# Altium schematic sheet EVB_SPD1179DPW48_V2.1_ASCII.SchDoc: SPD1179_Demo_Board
size A2; Date: 2024/07/12; Revision: V2.1; SheetNumber: 1; SheetTotal: 1
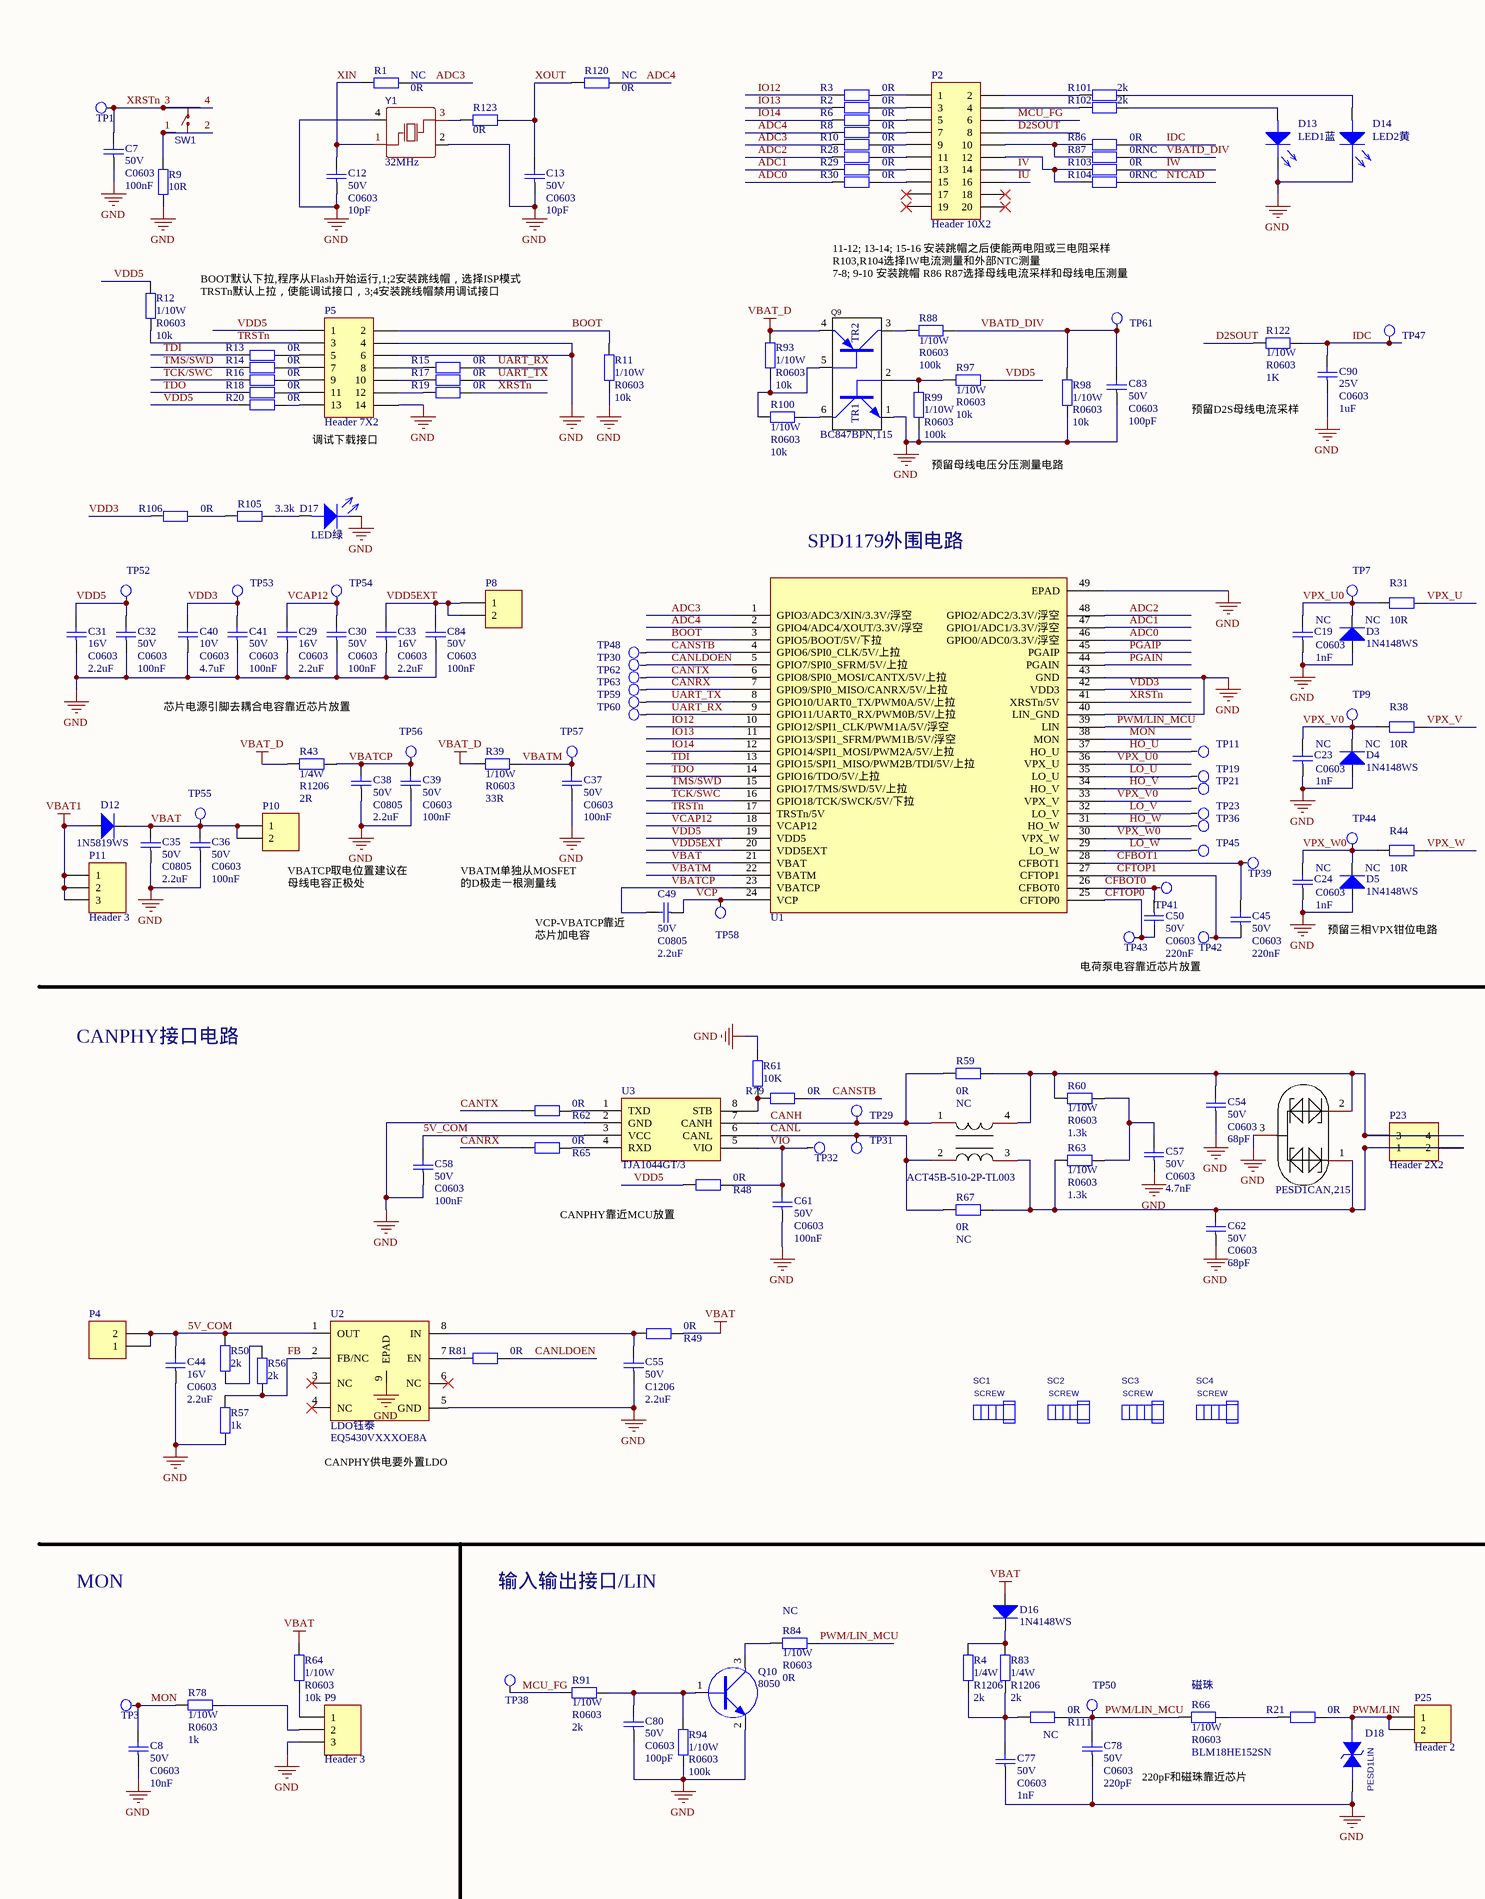
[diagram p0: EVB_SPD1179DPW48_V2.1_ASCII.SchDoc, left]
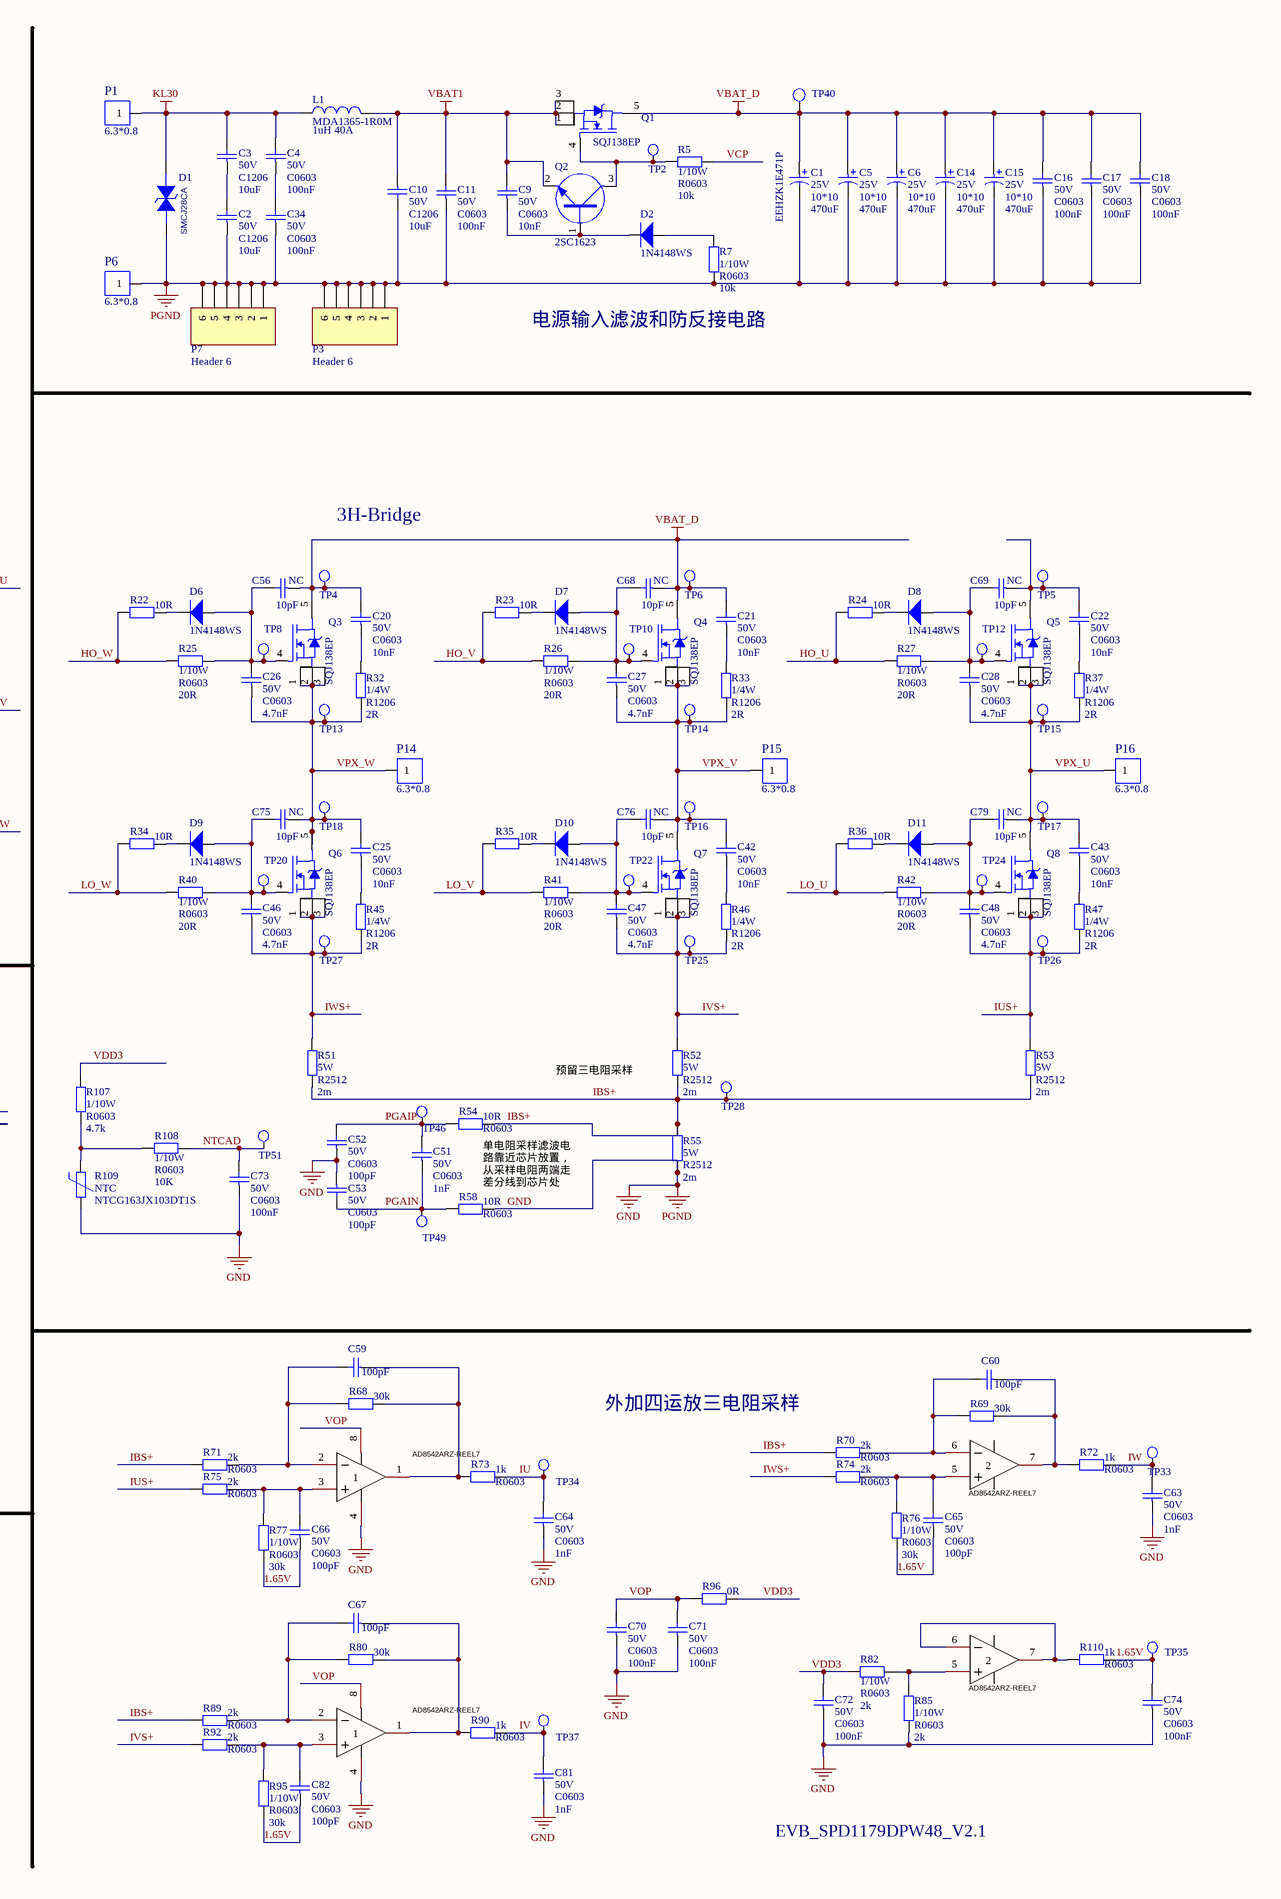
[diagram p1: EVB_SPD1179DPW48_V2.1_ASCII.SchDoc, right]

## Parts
C1  EEHZK1E471P  value 470uF  Voltage: 25V  Package: 10*10  [CAP-SMD_BD10.0-L10.3-W10.3-FD]
C2  value 10uF  Voltage: 50V  [C1206]  (hidden comment: CAP)
C3  value 10uF  Voltage: 50V  [C1206]  (hidden comment: CAP)
C4  value 100nF  Voltage: 50V  [C0603]  (hidden comment: CAP)
C5  value 470uF  Voltage: 25V  Package: 10*10  [CAP-SMD_BD10.0-L10.3-W10.3-FD]  (hidden comment: EEHZK1E471P)
C6  value 470uF  Voltage: 25V  Package: 10*10  [CAP-SMD_BD10.0-L10.3-W10.3-FD]  (hidden comment: EEHZK1E471P)
C7  value 100nF  Voltage: 50V  [C0603]  (hidden comment: CAP)
C8  value 10nF  Voltage: 50V  [C0603]  (hidden comment: CAP)
C9  value 10nF  Voltage: 50V  [C0603]  (hidden comment: CAP)
C10  value 10uF  Voltage: 50V  [C1206]  (hidden comment: CAP)
C11  value 100nF  Voltage: 50V  [C0603]  (hidden comment: CAP)
C12  value 10pF  Voltage: 50V  [C0603]  (hidden comment: CAP)
C13  value 10pF  Voltage: 50V  [C0603]  (hidden comment: CAP)
C14  value 470uF  Voltage: 25V  Package: 10*10  [CAP-SMD_BD10.0-L10.3-W10.3-FD]  (hidden comment: EEHZK1E471P)
C15  value 470uF  Voltage: 25V  Package: 10*10  [CAP-SMD_BD10.0-L10.3-W10.3-FD]  (hidden comment: EEHZK1E471P)
C16  value 100nF  Voltage: 50V  [C0603]  (hidden comment: CAP)
C17  value 100nF  Voltage: 50V  [C0603]  (hidden comment: CAP)
C18  value 100nF  Voltage: 50V  [C0603]  (hidden comment: CAP)
C19  NC  value 1nF  [C0603]
C20  value 10nF  Voltage: 50V  [C0603]  (hidden comment: CAP)
C21  value 10nF  Voltage: 50V  [C0603]  (hidden comment: CAP)
C22  value 10nF  Voltage: 50V  [C0603]  (hidden comment: CAP)
C23  NC  value 1nF  [C0603]
C24  NC  value 1nF  [C0603]
C25  value 10nF  Voltage: 50V  [C0603]  (hidden comment: CAP)
C26  value 4.7nF  Voltage: 50V  [C0603]  (hidden comment: CAP)
C27  value 4.7nF  Voltage: 50V  [C0603]  (hidden comment: CAP)
C28  value 4.7nF  Voltage: 50V  [C0603]  (hidden comment: CAP)
C29  value 2.2uF  Voltage: 16V  [C0603]  (hidden comment: CAP)
C30  value 100nF  Voltage: 50V  [C0603]  (hidden comment: CAP)
C31  value 2.2uF  Voltage: 16V  [C0603]  (hidden comment: CAP)
C32  value 100nF  Voltage: 50V  [C0603]  (hidden comment: CAP)
C33  value 2.2uF  Voltage: 16V  [C0603]  (hidden comment: CAP)
C34  value 100nF  Voltage: 50V  [C0603]  (hidden comment: CAP)
C35  value 2.2uF  Voltage: 50V  [C0805]  (hidden comment: CAP)
C36  value 100nF  Voltage: 50V  [C0603]  (hidden comment: CAP)
C37  value 100nF  Voltage: 50V  [C0603]  (hidden comment: CAP)
C38  value 2.2uF  Voltage: 50V  [C0805]  (hidden comment: CAP)
C39  value 100nF  Voltage: 50V  [C0603]  (hidden comment: CAP)
C40  value 4.7uF  Voltage: 10V  [C0603]  (hidden comment: CAP)
C41  value 100nF  Voltage: 50V  [C0603]  (hidden comment: CAP)
C42  value 10nF  Voltage: 50V  [C0603]  (hidden comment: CAP)
C43  value 10nF  Voltage: 50V  [C0603]  (hidden comment: CAP)
C44  value 2.2uF  Voltage: 16V  [C0603]  (hidden comment: CAP)
C45  value 220nF  Voltage: 50V  [C0603]  (hidden comment: CAP)
C46  value 4.7nF  Voltage: 50V  [C0603]  (hidden comment: CAP)
C47  value 4.7nF  Voltage: 50V  [C0603]  (hidden comment: CAP)
C48  value 4.7nF  Voltage: 50V  [C0603]  (hidden comment: CAP)
C49  value 2.2uF  Voltage: 50V  [C0805]  (hidden comment: CAP)
C50  value 220nF  Voltage: 50V  [C0603]  (hidden comment: CAP)
C51  value 1nF  Voltage: 50V  [C0603]  (hidden comment: CAP)
C52  value 100pF  Voltage: 50V  [C0603]  (hidden comment: CAP)
C53  value 100pF  Voltage: 50V  [C0603]  (hidden comment: CAP)
C54  value 68pF  Voltage: 50V  [C0603]  (hidden comment: CAP)
C55  value 2.2uF  Voltage: 50V  [C1206]  (hidden comment: CAP)
C56  NC  value 10pF  [C0603]
C57  value 4.7nF  Voltage: 50V  [C0603]  (hidden comment: CAP)
C58  value 100nF  Voltage: 50V  [C0603]  (hidden comment: CAP)
C59  value 100pF  [C0603]  (hidden comment: CAP)
C60  value 100pF  [C0603]  (hidden comment: CAP)
C61  value 100nF  Voltage: 50V  [C0603]  (hidden comment: CAP)
C62  value 68pF  Voltage: 50V  [C0603]  (hidden comment: CAP)
C63  value 1nF  Voltage: 50V  [C0603]  (hidden comment: CAP)
C64  value 1nF  Voltage: 50V  [C0603]  (hidden comment: CAP)
C65  value 100pF  Voltage: 50V  [C0603]  (hidden comment: CAP)
C66  value 100pF  Voltage: 50V  [C0603]  (hidden comment: CAP)
C67  value 100pF  [C0603]  (hidden comment: CAP)
C68  NC  value 10pF  [C0603]
C69  NC  value 10pF  [C0603]
C70  value 100nF  Voltage: 50V  [C0603]  (hidden comment: CAP)
C71  value 100nF  Voltage: 50V  [C0603]  (hidden comment: CAP)
C72  value 100nF  Voltage: 50V  [C0603]  (hidden comment: CAP)
C73  value 100nF  Voltage: 50V  [C0603]  (hidden comment: CAP)
C74  value 100nF  Voltage: 50V  [C0603]  (hidden comment: CAP)
C75  NC  value 10pF  [C0603]
C76  NC  value 10pF  [C0603]
C77  value 1nF  Voltage: 50V  [C0603]
C78  value 220pF  Voltage: 50V  [C0603]  (hidden comment: CAP)
C79  NC  value 10pF  [C0603]
C80  value 100pF  Voltage: 50V  [C0603]  (hidden comment: CAP)
C81  value 1nF  Voltage: 50V  [C0603]  (hidden comment: CAP)
C82  value 100pF  Voltage: 50V  [C0603]  (hidden comment: CAP)
C83  value 100pF  Voltage: 50V  [C0603]  (hidden comment: CAP)
C84  value 100nF  Voltage: 50V  [C0603]  (hidden comment: CAP)
C90  value 1uF  Voltage: 25V  [C0603]  (hidden comment: CAP)
D1  value SMCJ28CA  [SMC/DO-214AB/Bidirect]
D2  value 1N4148WS  [SODFL2513X100/SOD323F/SC-90]  (hidden comment: DIODE)
D3  NC  value 1N4148WS  [SODFL2513X100/SOD323F/SC-90]
D4  NC  value 1N4148WS  [SODFL2513X100/SOD323F/SC-90]
D5  NC  value 1N4148WS  [SODFL2513X100/SOD323F/SC-90]
D6  value 1N4148WS  [SODFL2513X100/SOD323F/SC-90]
D7  value 1N4148WS  [SODFL2513X100/SOD323F/SC-90]
D8  value 1N4148WS  [SODFL2513X100/SOD323F/SC-90]
D9  value 1N4148WS  [SODFL2513X100/SOD323F/SC-90]
D10  value 1N4148WS  [SODFL2513X100/SOD323F/SC-90]
D11  value 1N4148WS  [SODFL2513X100/SOD323F/SC-90]
D12  value 1N5819WS  [SOD-323_L1.8-W1.3-LS2.5-RD]  (hidden comment: DIODE)
D13  value LED1蓝  [LED0603-R-RD]  (hidden comment: D_LED_0603)
D14  value LED2黄  [LED0603-R-RD]  (hidden comment: D_LED_0603)
D15  PESD1CAN,215  [SOT-23_L2.9-W1.3-P1.90-LS2.4-BR]
D16  value 1N4148WS  [SODFL2513X100/SOD323F/SC-90]
D17  value LED绿  [LED0603-R-RD]  (hidden comment: D_LED_0603)
D18  value PESD1LIN  [SOD-323_L1.7-W1.3-LS2.5-BI]  (hidden comment: TVS)
L1  1uH 40A  value MDA1365-1R0M  [IND-SMD_L12.6-W13.5]
L2  ACT45B-510-2P-TL003  [IND-SMD_4P-L4.5-W3.2-TL]
P1  Package: 6.3*0.8  [CON_63X08_P1]  (hidden comment: P_CON-1PIN)
P2  Header 10X2  [HDR2X10]
P3  Header 6  [HDR1X6]
P4  (no value)  [HDR1X2]
P5  Header 7X2  [HDR2X7]
P6  Package: 6.3*0.8  [CON_63X08_P1]  (hidden comment: P_CON-1PIN)
P7  Header 6  [HDR1X6]
P8  (no value)  [HDR1X2]
P9  Header 3  [HDR1X3]
P10  (no value)  [HDR1X2]
P11  Header 3  [HDR1X3]
P14  Package: 6.3*0.8  [CON_63X08_P1]  (hidden comment: P_CON-1PIN)
P15  Package: 6.3*0.8  [CON_63X08_P1]  (hidden comment: P_CON-1PIN)
P16  Package: 6.3*0.8  [CON_63X08_P1]  (hidden comment: P_CON-1PIN)
P23  Header 2X2  [HDR2X2]
P25  Header 2  [HDR1X2]
Q1  SQJ138EP  [PowerPAK_SO-8L_3_VIS]
Q2  value 2SC1623  [SOT95P240X110-3/SOT23/TO-236]  (hidden comment: NPN)
Q3  SQJ138EP  [PowerPAK_SO-8L_3_VIS]
Q4  SQJ138EP  [PowerPAK_SO-8L_3_VIS]
Q5  SQJ138EP  [PowerPAK_SO-8L_3_VIS]
Q6  SQJ138EP  [PowerPAK_SO-8L_3_VIS]
Q7  SQJ138EP  [PowerPAK_SO-8L_3_VIS]
Q8  SQJ138EP  [PowerPAK_SO-8L_3_VIS]
Q9  BC847BPN,115  [SOT-363_L2.0-W1.3-P0.65-LS2.1-TL]
Q10  value 8050  [SOT95P240X110-3/SOT23/TO-236]  (hidden comment: NPN)
R1  NC  value 0R  [R0603]
R2  value 0R  [R0603]  (hidden comment: RES)
R3  value 0R  [R0603]  (hidden comment: RES)
R4  value 2k  Power: 1/4W  [R1206]
R5  value 10k  Power: 1/10W  [R0603]  (hidden comment: RES)
R6  value 0R  [R0603]  (hidden comment: RES)
R7  value 10k  Power: 1/10W  [R0603]  (hidden comment: RES)
R8  value 0R  [R0603]  (hidden comment: RES)
R9  value 10R  [R0603]  (hidden comment: RES)
R10  value 0R  [R0603]  (hidden comment: RES)
R11  value 10k  Power: 1/10W  [R0603]  (hidden comment: RES)
R12  value 10k  Power: 1/10W  [R0603]  (hidden comment: RES)
R13  value 0R  [R0603]  (hidden comment: RES)
R14  value 0R  [R0603]  (hidden comment: RES)
R15  value 0R  [R0603]  (hidden comment: RES)
R16  value 0R  [R0603]  (hidden comment: RES)
R17  value 0R  [R0603]  (hidden comment: RES)
R18  value 0R  [R0603]  (hidden comment: RES)
R19  value 0R  [R0603]  (hidden comment: RES)
R20  value 0R  [R0603]  (hidden comment: RES)
R21  value 0R  [R0603]  (hidden comment: RES)
R22  value 10R  [R0603]
R23  value 10R  [R0603]
R24  value 10R  [R0603]
R25  value 20R  Power: 1/10W  [R0603]
R26  value 20R  Power: 1/10W  [R0603]
R27  value 20R  Power: 1/10W  [R0603]
R28  value 0R  [R0603]  (hidden comment: RES)
R29  value 0R  [R0603]  (hidden comment: RES)
R30  value 0R  [R0603]  (hidden comment: RES)
R31  value 10R  [R0603]  (hidden comment: RES)
R32  value 2R  Power: 1/4W  [R1206]  (hidden comment: RES)
R33  value 2R  Power: 1/4W  [R1206]  (hidden comment: RES)
R34  value 10R  [R0603]
R35  value 10R  [R0603]
R36  value 10R  [R0603]
R37  value 2R  Power: 1/4W  [R1206]  (hidden comment: RES)
R38  value 10R  [R0603]  (hidden comment: RES)
R39  value 33R  Power: 1/10W  [R0603]
R40  value 20R  Power: 1/10W  [R0603]
R41  value 20R  Power: 1/10W  [R0603]
R42  value 20R  Power: 1/10W  [R0603]
R43  value 2R  Power: 1/4W  [R1206]  (hidden comment: RES)
R44  value 10R  [R0603]  (hidden comment: RES)
R45  value 2R  Power: 1/4W  [R1206]  (hidden comment: RES)
R46  value 2R  Power: 1/4W  [R1206]  (hidden comment: RES)
R47  value 2R  Power: 1/4W  [R1206]  (hidden comment: RES)
R48  value 0R  [R0603]  (hidden comment: RES)
R49  value 0R  [R0603]  (hidden comment: RES)
R50  value 2k  [R0603]  (hidden comment: RES)
R51  value 2m  Power: 5W  [R2512]  (hidden comment: RES)
R52  value 2m  Power: 5W  [R2512]  (hidden comment: RES)
R53  value 2m  Power: 5W  [R2512]  (hidden comment: RES)
R54  value 10R  [R0603]  (hidden comment: RES)
R55  value 2m  Power: 5W  [R2512]  (hidden comment: RES)
R56  value 2k  [R0603]  (hidden comment: RES)
R57  value 1k  [R0603]  (hidden comment: RES)
R58  value 10R  [R0603]  (hidden comment: RES)
R59  NC  value 0R  [R0402]
R60  value 1.3k  Power: 1/10W  [R0603]  (hidden comment: RES)
R61  value 10K  [R0603]  (hidden comment: RES)
R62  value 0R  [R0603]  (hidden comment: RES)
R63  value 1.3k  Power: 1/10W  [R0603]  (hidden comment: RES)
R64  value 10k  Power: 1/10W  [R0603]  (hidden comment: RES)
R65  value 0R  [R0603]  (hidden comment: RES)
R66  磁珠  value BLM18HE152SN  Power: 1/10W  [R0603]
R67  NC  value 0R  [R0402]
R68  value 30k  [R0603]  (hidden comment: RES)
R69  value 30k  [R0603]  (hidden comment: RES)
R70  value 2k  [R0603]  (hidden comment: RES)
R71  value 2k  [R0603]  (hidden comment: RES)
R72  value 1k  [R0603]  (hidden comment: RES)
R73  value 1k  [R0603]  (hidden comment: RES)
R74  value 2k  [R0603]  (hidden comment: RES)
R75  value 2k  [R0603]  (hidden comment: RES)
R76  value 30k  Power: 1/10W  [R0603]  (hidden comment: RES)
R77  value 30k  Power: 1/10W  [R0603]  (hidden comment: RES)
R78  value 1k  Power: 1/10W  [R0603]  (hidden comment: RES)
R79  value 0R  [R0603]  (hidden comment: RES)
R80  value 30k  [R0603]  (hidden comment: RES)
R81  value 0R  [R0603]  (hidden comment: RES)
R82  value 2k  Power: 1/10W  [R0603]  (hidden comment: RES)
R83  value 2k  Power: 1/4W  [R1206]
R84  NC  value 0R  Power: 1/10W  [R0603]
R85  value 2k  Power: 1/10W  [R0603]  (hidden comment: RES)
R86  value 0R  [R0603]
R87  NC  value 0R  [R0603]
R88  value 100k  Power: 1/10W  [R0603]  (hidden comment: RES)
R89  value 2k  [R0603]  (hidden comment: RES)
R90  value 1k  [R0603]  (hidden comment: RES)
R91  value 2k  Power: 1/10W  [R0603]  (hidden comment: RES)
R92  value 2k  [R0603]  (hidden comment: RES)
R93  value 10k  Power: 1/10W  [R0603]  (hidden comment: RES)
R94  value 100k  Power: 1/10W  [R0603]  (hidden comment: RES)
R95  value 30k  Power: 1/10W  [R0603]  (hidden comment: RES)
R96  value 0R  [R0603]
R97  value 10k  Power: 1/10W  [R0603]  (hidden comment: RES)
R98  value 10k  Power: 1/10W  [R0603]  (hidden comment: RES)
R99  value 100k  Power: 1/10W  [R0603]  (hidden comment: RES)
R100  value 10k  Power: 1/10W  [R0603]  (hidden comment: RES)
R101  value 2k  [R0603]  (hidden comment: RES)
R102  value 2k  [R0603]  (hidden comment: RES)
R103  value 0R  [R0603]
R104  NC  value 0R  [R0603]
R105  value 3.3k  [R0603]  (hidden comment: RES)
R106  value 0R  [R0603]  (hidden comment: RES)
R107  value 4.7k  Power: 1/10W  [R0603]  (hidden comment: RES)
R108  value 10K  Power: 1/10W  [R0603]  (hidden comment: RES)
R109  NTC  value NTCG163JX103DT1S  [R0603]
R110  value 1k  [R0603]  (hidden comment: RES)
R111  NC  value 0R  [R0603]
R120  NC  value 0R  [R0603]
R122  value 1K  Power: 1/10W  [R0603]  (hidden comment: RES)
R123  value 0R  [R0603]  (hidden comment: RES)
SC1  SCREW  [pad]  (value not drawn)
SC2  SCREW  [pad]  (value not drawn)
SC3  SCREW  [pad]  (value not drawn)
SC4  SCREW  [pad]  (value not drawn)
SW1  TS-1095PD-A6B2-D2  [KEY-TH_4P-L6.0-W6.0-P3.90-LS6.5]  (value not drawn)
TP1  TEST-Point  [TP-1.0]  (value not drawn)  (no BOM)
TP2  TEST-Point  [TP-1.0]  (value not drawn)  (no BOM)
TP3  TEST-Point  [TP-1.0]  (value not drawn)  (no BOM)
TP4  TEST-Point  [TP-1.0]  (value not drawn)  (no BOM)
TP5  TEST-Point  [TP-1.0]  (value not drawn)  (no BOM)
TP6  TEST-Point  [TP-1.0]  (value not drawn)  (no BOM)
TP7  TEST-Point  [TP-1.0]  (value not drawn)  (no BOM)
TP8  TEST-Point  [TP-1.0]  (value not drawn)  (no BOM)
TP9  TEST-Point  [TP-1.0]  (value not drawn)  (no BOM)
TP10  TEST-Point  [TP-1.0]  (value not drawn)  (no BOM)
TP11  TEST-Point  [TP-1.0]  (value not drawn)  (no BOM)
TP12  TEST-Point  [TP-1.0]  (value not drawn)  (no BOM)
TP13  TEST-Point  [TP-1.0]  (value not drawn)  (no BOM)
TP14  TEST-Point  [TP-1.0]  (value not drawn)  (no BOM)
TP15  TEST-Point  [TP-1.0]  (value not drawn)  (no BOM)
TP16  TEST-Point  [TP-1.0]  (value not drawn)  (no BOM)
TP17  TEST-Point  [TP-1.0]  (value not drawn)  (no BOM)
TP18  TEST-Point  [TP-1.0]  (value not drawn)  (no BOM)
TP19  TEST-Point  [TP-1.0]  (value not drawn)  (no BOM)
TP20  TEST-Point  [TP-1.0]  (value not drawn)  (no BOM)
TP21  TEST-Point  [TP-1.0]  (value not drawn)  (no BOM)
TP22  TEST-Point  [TP-1.0]  (value not drawn)  (no BOM)
TP23  TEST-Point  [TP-1.0]  (value not drawn)  (no BOM)
TP24  TEST-Point  [TP-1.0]  (value not drawn)  (no BOM)
TP25  TEST-Point  [TP-1.0]  (value not drawn)  (no BOM)
TP26  TEST-Point  [TP-1.0]  (value not drawn)  (no BOM)
TP27  TEST-Point  [TP-1.0]  (value not drawn)  (no BOM)
TP28  TEST-Point  [TP-1.0]  (value not drawn)  (no BOM)
TP29  TEST-Point  [TP-1.0]  (value not drawn)  (no BOM)
TP30  TEST-Point  [TP-1.0]  (value not drawn)  (no BOM)
TP31  TEST-Point  [TP-1.0]  (value not drawn)  (no BOM)
TP32  TEST-Point  [TP-1.0]  (value not drawn)  (no BOM)
TP33  TEST-Point  [TP-1.0]  (value not drawn)  (no BOM)
TP34  TEST-Point  [TP-1.0]  (value not drawn)  (no BOM)
TP35  TEST-Point  [TP-1.0]  (value not drawn)  (no BOM)
TP36  TEST-Point  [TP-1.0]  (value not drawn)  (no BOM)
TP37  TEST-Point  [TP-1.0]  (value not drawn)  (no BOM)
TP38  TEST-Point  [TP-1.0]  (value not drawn)  (no BOM)
TP39  TEST-Point  [TP-1.0]  (value not drawn)  (no BOM)
TP40  TEST-SMD  [TEST-SMD_L2.7-W1.0]  (value not drawn)  (no BOM)
TP41  TEST-Point  [TP-1.0]  (value not drawn)  (no BOM)
TP42  TEST-Point  [TP-1.0]  (value not drawn)  (no BOM)
TP43  TEST-Point  [TP-1.0]  (value not drawn)  (no BOM)
TP44  TEST-Point  [TP-1.0]  (value not drawn)  (no BOM)
TP45  TEST-Point  [TP-1.0]  (value not drawn)  (no BOM)
TP46  TEST-Point  [TP-1.0]  (value not drawn)  (no BOM)
TP47  TEST-Point  [TP-1.0]  (value not drawn)  (no BOM)
TP48  TEST-Point  [TP-1.0]  (value not drawn)  (no BOM)
TP49  TEST-Point  [TP-1.0]  (value not drawn)  (no BOM)
TP50  TEST-Point  [TP-1.0]  (value not drawn)  (no BOM)
TP51  TEST-Point  [TP-1.0]  (value not drawn)  (no BOM)
TP52  TEST-Point  [TP-1.0]  (value not drawn)  (no BOM)
TP53  TEST-Point  [TP-1.0]  (value not drawn)  (no BOM)
TP54  TEST-Point  [TP-1.0]  (value not drawn)  (no BOM)
TP55  TEST-Point  [TP-1.0]  (value not drawn)  (no BOM)
TP56  TEST-Point  [TP-1.0]  (value not drawn)  (no BOM)
TP57  TEST-Point  [TP-1.0]  (value not drawn)  (no BOM)
TP58  TEST-Point  [TP-1.0]  (value not drawn)  (no BOM)
TP59  TEST-Point  [TP-1.0]  (value not drawn)  (no BOM)
TP60  TEST-Point  [TP-1.0]  (value not drawn)  (no BOM)
TP61  TEST-Point  [TP-1.0]  (value not drawn)  (no BOM)
TP62  TEST-Point  [TP-1.0]  (value not drawn)  (no BOM)
TP63  TEST-Point  [TP-1.0]  (value not drawn)  (no BOM)
U1  SPD1179  [QFN48-0.5-1179-QFN50P700X700X90_HS-49M]  (value not drawn)
U2  LDO钰泰  value EQ5430VXXXOE8A  [ESOP-8_L4.9-W3.9-P1.27-LS6.0-BL-EP]
U3  TJA1044GT/3  [SOIC-8_L4.9-W3.9-P1.27-LS6.0-BL]
U4  AD8542ARZ-REEL7  [SOIC-8_L4.9-W3.9-P1.27-LS6.0-BL]  (parts A,B of 2)
U5  AD8542ARZ-REEL7  [SOIC-8_L4.9-W3.9-P1.27-LS6.0-BL]  (parts A,B of 2)
Y1  32MHz  [CRYSTAL-SMD_4P-L3.2-W2.5-BL]

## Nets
GND: C1.2 C2.1 C5.2 C6.2 C7.1 C8.1 C10.2 C11.1 C12.1 C13.1 C14.2 C15.2 C16.1 C17.1 C18.1 C19.1 C23.1 C24.1 C29.1 C30.1 C31.1 C32.1 C33.1 C34.1 C35.1 C36.1 C37.1 C38.1 C39.1 C40.1 C41.1 C44.1 C52.1 C53.1 C54.1 C55.1 C57.1 C58.1 C61.1 C62.1 C63.1 C64.1 C70.1 C71.1 C72.1 C73.1 C74.1 C77.1 C78.1 C80.1 C81.1 C83.1 C84.1 C90.1 D1.1(CATHODE1) D3.2(A) D4.2(A) D5.2(A) D13.2(K) D14.2(K) D15.3 D17.2(K) D18.1(CATHODE1) P3.1 P3.2 P3.3 P3.4 P3.5 P3.6 P5.4 P5.6 P5.14 P6.1 P7.1 P7.2 P7.3 P7.4 P7.5 P7.6 P9.3 Q9.1(N_E) Q10.2(2E) R7.1 R9.2 R11.1 R55.1 R57.1 R58.1 R61.1 R85.2 R94.1 R98.2 R99.1 R109.2 U1.40(LIN_GND) U1.43(GND) U1.49(EPAD) U2.5(GND) U2.9(EPAD) U3.2(GND) U4.4(V-) U5.4(V-) Y1.2(GND) Y1.4(GND)  [also labelled PGND]
KL30: C3.2 C4.2 D1.2(CATHODE2) L1.1 P1.1
VBAT: C35.2 C36.2 D12.1(K) D16.2(A) P10.1 P10.2 R49.1 R64.2 TP55.1 U1.21(VBAT)
VBAT1: C9.2 C10.1 C11.2 D12.2(A) L1.2 P11.1 P11.2 P11.3 Q1.1(SOURCE) Q1.2(SOURCE) Q1.3(SOURCE) Q2.2(2E)
VBAT_D: C1.1 C5.1 C6.1 C14.1 C15.1 C16.2 C17.2 C18.2 C20.2 C21.2 C56.1 C68.1 Q1.5(DRAIN) Q3.5(DRAIN) Q4.5(DRAIN) Q9.4(P_E) R39.2 R43.1 R93.1 TP4.1 TP6.1 TP40.1
1.65V: C65.1 C66.1 C74.2 C82.1 R76.1 R77.1 R95.1 R110.1 TP35.1
5V_COM: C44.2 C58.2 P4.1 P4.2 R50.2 U2.1(OUT) U3.3(VCC)
ADC0: R30.2 U1.46(GPIO0/ADC0/3.3V/浮空)
ADC1: R29.2 U1.47(GPIO1/ADC1/3.3V/浮空)
ADC2: R28.2 U1.48(GPIO2/ADC2/3.3V/浮空)
ADC3: R1.2 R10.2 U1.1(GPIO3/ADC3/XIN/3.3V/浮空)
ADC4: R8.2 R120.2 U1.2(GPIO4/ADC4/XOUT/3.3V/浮空)
BOOT: P5.2 R11.2 U1.3(GPIO5/BOOT/5V/下拉)
CANH: L2.1 R59.1 TP29.1 U3.7(CANH)
CANL: L2.2 R67.1 TP31.1 U3.6(CANL)
CANLDOEN: R81.1 TP30.1 U1.5(GPIO7/SPI0_SFRM/5V/上拉)
CANRX: R65.2 TP63.1 U1.7(GPIO9/SPI0_MISO/CANRX/5V/上拉)
CANSTB: R79.1 TP48.1 U1.4(GPIO6/SPI0_CLK/5V/上拉)
CANTX: R62.2 TP62.1 U1.6(GPIO8/SPI0_MOSI/CANTX/5V/上拉)
CFBOT0: C50.1 TP41.1 U1.26(CFBOT0)
CFBOT1: C45.2 TP39.1 U1.28(CFBOT1)
CFTOP0: C50.2 TP43.1 U1.25(CFTOP0)
CFTOP1: C45.1 TP42.1 U1.27(CFTOP1)
D2SOUT: P2.8 R122.2
FB: R56.1 R57.2 U2.2(FB/NC)
HO_U: R24.2 R27.2 TP11.1 U1.37(HO_U)
HO_V: R23.2 R26.2 TP21.1 U1.34(HO_V)
HO_W: R22.2 R25.2 TP36.1 U1.31(HO_W)
IBS+: R51.1 R52.1 R53.1 R54.1 R55.2 R70.2 R71.2 R89.2 TP28.1
IDC: C90.2 R86.1 R122.1 TP47.1
IO12: R3.2 U1.10(GPIO12/SPI1_CLK/PWM1A/5V/浮空)
IO13: R2.2 U1.11(GPIO13/SPI1_SFRM/PWM1B/5V/浮空)
IO14: R6.2 U1.12(GPIO14/SPI1_MOSI/PWM2A/5V/上拉)
IU: C64.2 P2.16 R73.1 TP34.1
IUS+: C48.1 Q8.1(SOURCE) Q8.2(SOURCE) Q8.3(SOURCE) R47.2 R53.2 R75.2 TP26.1
IV: C81.2 P2.14 R90.1 TP37.1
IVS+: C47.1 Q7.1(SOURCE) Q7.2(SOURCE) Q7.3(SOURCE) R46.2 R52.2 R92.2 TP25.1
IW: C63.2 R72.1 R103.1 TP33.1
IWS+: C46.1 Q6.1(SOURCE) Q6.2(SOURCE) Q6.3(SOURCE) R45.2 R51.2 R74.2 TP27.1
LO_U: R36.2 R42.2 TP19.1 U1.35(LO_U)
LO_V: R35.2 R41.2 TP23.1 U1.32(LO_V)
LO_W: R34.2 R40.2 TP45.1 U1.29(LO_W)
MCU_FG: P2.6 R91.2 TP38.1
MON: C8.2 R78.1 TP3.1 U1.38(MON)
NTCAD: C73.2 R104.1 R108.2 TP51.1
PGAIN: C51.1 C53.2 R58.2 TP49.1 U1.44(PGAIN)
PGAIP: C51.2 C52.2 R54.2 TP46.1 U1.45(PGAIP)
PWM/LIN: D18.2(CATHODE2) P25.1 P25.2 R21.1
PWM/LIN_MCU: C78.2 R66.2 R84.1 R111.1 TP50.1 U1.39(LIN)
TCK/SWC: R16.2 U1.16(GPIO18/TCK/SWCK/5V/下拉)
TDI: R13.2 U1.13(GPIO15/SPI1_MISO/PWM2B/TDI/5V/上拉)
TDO: R18.2 U1.14(GPIO16/TDO/5V/上拉)
TMS/SWD: R14.2 U1.15(GPIO17/TMS/SWD/5V/上拉)
TRSTn: P5.3 R12.1 U1.17(TRSTn/5V)
UART_RX: R15.1 TP60.1 U1.9(GPIO11/UART0_RX/PWM0B/5V/上拉)
UART_TX: R17.1 TP59.1 U1.8(GPIO10/UART0_TX/PWM0A/5V/上拉)
VBATCP: C38.2 C39.2 C49.2 R43.2 TP56.1 U1.23(VBATCP)
VBATD_DIV: C83.2 R87.1 R88.1 R98.1 TP61.1
VBATM: C37.2 R39.1 TP57.1 U1.22(VBATM)
VCAP12: C29.2 C30.2 TP54.1 U1.18(VCAP12)
VCP: C49.1 R5.1 TP58.1 U1.24(VCP)
VDD3: C40.2 C41.2 C72.2 R82.1 R96.1 R106.2 R107.2 TP53.1 U1.42(VDD3)
VDD5: C31.2 C32.2 P5.1 R12.2 R20.2 R48.2 R97.1 TP52.1 U1.19(VDD5)
VDD5EXT: C33.2 C84.2 P8.1 P8.2 U1.20(VDD5EXT)
VIO: C61.2 R48.1 TP32.1 U3.5(VIO)
VOP: C70.2 C71.2 R96.2 U4.8(V+) U5.8(V+)
VPX_U: C28.1 C43.2 C79.1 P16.1 Q5.1(SOURCE) Q5.2(SOURCE) Q5.3(SOURCE) Q8.5(DRAIN) R31.1 R37.2 TP15.1 TP17.1
VPX_U0: C19.2 D3.1(K) R31.2 TP7.1 U1.36(VPX_U)
VPX_V: C27.1 C42.2 C76.1 P15.1 Q4.1(SOURCE) Q4.2(SOURCE) Q4.3(SOURCE) Q7.5(DRAIN) R33.2 R38.1 TP14.1 TP16.1
VPX_V0: C23.2 D4.1(K) R38.2 TP9.1 U1.33(VPX_V)
VPX_W: C25.2 C26.1 C75.1 P14.1 Q3.1(SOURCE) Q3.2(SOURCE) Q3.3(SOURCE) Q6.5(DRAIN) R32.2 R44.1 TP13.1 TP18.1
VPX_W0: C24.2 D5.1(K) R44.2 TP44.1 U1.30(VPX_W)
XIN: C12.2 R1.1 Y1.1(OSC1)
XOUT: C13.2 R120.1 R123.2
XRSTn: C7.2 R19.1 SW1.3 SW1.4 TP1.1 U1.41(XRSTn/5V)
NetC2_2: C2.2 C3.1
NetC4_1: C4.1 C34.2
NetC9_1: C9.1 D2.1(K) Q2.1(1B)
NetC20_1: C20.1 R32.1
NetC21_1: C21.1 R33.1
NetC22_1: C22.1 R37.1
NetC22_2: C22.2 C69.1 Q5.5(DRAIN) TP5.1
NetC25_1: C25.1 R45.1
NetC26_2: C26.2 C56.2 D6.2(A) Q3.4(GATE) R25.1 TP8.1
NetC27_2: C27.2 C68.2 D7.2(A) Q4.4(GATE) R26.1 TP10.1
NetC28_2: C28.2 C69.2 D8.2(A) Q5.4(GATE) R27.1 TP12.1
NetC42_1: C42.1 R46.1
NetC43_1: C43.1 R47.1
NetC46_2: C46.2 C75.2 D9.2(A) Q6.4(GATE) R40.1 TP20.1
NetC47_2: C47.2 C76.2 D10.2(A) Q7.4(GATE) R41.1 TP22.1
NetC48_2: C48.2 C79.2 D11.2(A) Q8.4(GATE) R42.1 TP24.1
NetC54_2: C54.2 D15.2 L2.4 P23.3 P23.4 R59.2 R60.2
NetC55_2: C55.2 R49.2 U2.8(IN)
NetC57_2: C57.2 R60.1 R63.1
NetC59_1: C59.1 R68.1 R73.2 U4.1(OUT)
NetC59_2: C59.2 R68.2 R71.1 U4.2(IN-)
NetC60_1: C60.1 R69.1 R72.2 U4.7(OUT)
NetC60_2: C60.2 R69.2 R70.1 U4.6(IN-)
NetC62_2: C62.2 D15.1 L2.3 P23.1 P23.2 R63.2 R67.2
NetC65_2: C65.2 R74.1 R76.2 U4.5(IN+)
NetC66_2: C66.2 R75.1 R77.2 U4.3(IN+)
NetC67_1: C67.1 R80.1 R90.2 U5.1(OUT)
NetC67_2: C67.2 R80.2 R89.1 U5.2(IN-)
NetC77_2: C77.2 R4.1 R83.1 R111.2
NetC80_2: C80.2 Q10.1(1B) R91.1 R94.2
NetC82_2: C82.2 R92.1 R95.2 U5.3(IN+)
NetD2_2: D2.2(A) R7.2
NetD6_1: D6.1(K) R22.1
NetD7_1: D7.1(K) R23.1
NetD8_1: D8.1(K) R24.1
NetD9_1: D9.1(K) R34.1
NetD10_1: D10.1(K) R35.1
NetD11_1: D11.1(K) R36.1
NetD13_1: D13.1(A) R102.2
NetD14_1: D14.1(A) R101.2
NetD16_1: D16.1(K) R4.2 R83.2
NetD17_1: D17.1(A) R105.2
NetP2_1: P2.1 R3.1
NetP2_2: P2.2 R101.1
NetP2_3: P2.3 R2.1
NetP2_4: P2.4 R102.1
NetP2_5: P2.5 R6.1
NetP2_7: P2.7 R8.1
NetP2_9: P2.9 R10.1
NetP2_10: P2.10 R86.2 R87.2
NetP2_11: P2.11 R28.1
NetP2_12: P2.12 R103.2 R104.2
NetP2_13: P2.13 R29.1
NetP2_15: P2.15 R30.1
NetP5_5: P5.5 R13.1
NetP5_7: P5.7 R14.1
NetP5_8: P5.8 R15.2
NetP5_9: P5.9 R16.1
NetP5_10: P5.10 R17.2
NetP5_11: P5.11 R18.1
NetP5_12: P5.12 R19.2
NetP5_13: P5.13 R20.1
NetP9_1: P9.1 R64.1
NetP9_2: P9.2 R78.2
NetQ1_4: Q1.4(GATE) Q2.3(3C) R5.2 TP2.1
NetQ9_2: Q9.2(N_B) R97.2 R99.2
NetQ9_3: Q9.3(P_C) R88.2
NetQ9_5: Q9.5(P_B) R93.2 R100.1
NetQ9_6: Q9.6(N_C) R100.2
NetQ10_3: Q10.3(3C) R84.2
NetR9_1: R9.1 SW1.1 SW1.2
NetR21_2: R21.2 R66.1
NetR50_1: R50.1 R56.2
NetR61_2: R61.2 R79.2 U3.8(STB)
NetR62_1: R62.1 U3.1(TXD)
NetR65_1: R65.1 U3.4(RXD)
NetR81_2: R81.2 U2.7(EN)
NetR82_2: R82.2 R85.1 U5.5(IN+)
NetR105_1: R105.1 R106.1
NetR107_1: R107.1 R108.1 R109.1
NetR110_2: R110.2 U5.6(IN-) U5.7(OUT)
NetR123_1: R123.1 Y1.3(OSC2)

Not connected (* = marked no-connect by the designer): P2 17* 18* 19* 20*; U2 3(NC)* 4(NC)* 6(NC)*

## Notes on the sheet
- 11-12; 13-14; 15-16 安装跳帽之后使能两电阻或三电阻采样
  R103,R104选择IW电流测量和外部NTC测量
  7-8; 9-10 安装跳帽 R86 R87选择母线电流采样和母线电压测量
- (near P5) BOOT默认下拉,程序从Flash开始运行,1;2安装跳线帽，选择ISP模式
  TRSTn默认上拉，使能调试接口，3;4安装跳线帽禁用调试接口
- 电源输入滤波和防反接电路
- (near C90) 预留D2S母线电流采样
- (near P5) 调试下载接口
- 预留母线电压分压测量电路
- 3H-Bridge
- (near U1) SPD1179外围电路
- 芯片电源引脚去耦合电容靠近芯片放置
- (near P10) VBATCP取电位置建议在母线电容正极处
- VBATM单独从MOSFET的D极走一根测量线
- (near C49) VCP-VBATCP靠近芯片加电容
- 电荷泵电容靠近芯片放置
- 预留三相VPX钳位电路
- CANPHY接口电路
- (near R52) 预留三电阻采样
- (near R48) CANPHY靠近MCU放置
- 单电阻采样滤波电路靠近芯片放置，从采样电阻两端走差分线到芯片处
- (near U2) CANPHY供电要外置LDO
- 外加四运放三电阻采样
- MON
- 输入输出接口/LIN
- 220pF和磁珠靠近芯片
- EVB_SPD1179DPW48_V2.1

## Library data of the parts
C1 C5 C6 C14 C15 = CE_50V_220uF_10*10: Capacitor polarized
C2 C3 C10 C55 = C_1206_10%_1: MLCC
C4 C7-C9 C11-C13 C16-C18 C20-C22 C25-C34 C36 C37 C39-C48 C50-C54 C57 C58 C61-C66 C70-C74 C77 C78 C80-C84 C90 = C_0603_10%_1: MLCC
C19 C23 C24 C56 C59 C60 C67-C69 C75 C76 C79 = C_0603_10%_1: MLCC; Voltage: 50V
C35 C38 C49 = C_0805_10%_1: MLCC
D1 = D_TVS_SMC: TVS Bidirectional
D2-D11 D16 = D_1N4148WS: Diode SOD323
D12 = D_SMA
D15 = D_PESD1CAN,215: Manufacturer: Nexperia(安世); Add into BOM: yes; Polarity: Bidirectional; Voltage - Reverse Standoff (Typ): 24V; Voltage - Breakdown (Min): 25.4V; Voltage - Clamping (Max) @ Ipp: 70V; Current - Peak Pulse (10/1000μs): 3A
D18 = D_ESD_BI_SOD323: ESD TVS Bidirectional
L1 = L_SER2000
L2 = L_ACT45B-510-2P-TL003: Manufacturer: TDK; Add into BOM: yes; Number of Lines: 2; Impedance @ Frequency: 2.8kΩ@10MHz; Inductance @ Frequency: 51uH@100kHz; Current Rating: 200mA; DC Resistance (DCR): 1Ω; Voltage Rating - DC: 50V; Withstanding Voltage: 250V@2Secs
P1 P6 P14-P16 = P_CON-1PIN: Insert terminal,快接端子 6.3mm*0.8厚 插片
P2 = Header 10X2: Header, 10-Pin, Dual row
P3 P7 = Header 6: Header, 6-Pin
P4 P8 P10 P25 = Header 2: Header, 2-Pin
P5 = Header 7X2: Header, 7-Pin, Dual row
P9 P11 = Header 3: Header, 3-Pin
P23 = Header 2X2: Header, 2-Pin, Dual row
Q1 Q3-Q8 = Q_N_DFN-8L_5*6: N-CHANNEL; Id: 330A; Vds: 40V
Q2 Q10 = Q_8050
Q9 = Q_BC847BPN,115: Manufacturer: Nexperia(安世); Add into BOM: yes; Transistor Type: NPN+PNP; Collector Current (Ic): 100mA; Collector-Emitter Breakdown Voltage (Vceo): 45V; Power Dissipation (Pd): 300mW; DC Current Gain (hFE@Ic,Vce): 200@2mA,5V; Transition Frequency (fT): 100MHz; Collector Cut-Off Current (Icbo): 15nA; Collector-Emitter Saturation Voltage (VCE(sat)@Ic,Ib): 300mV@100mA,5mA
R1-R3 R6 R8-R10 R13-R24 R28-R31 R34-R36 R38 R44 R48-R50 R54 R56-R58 R61 R62 R65 R68-R75 R79-R81 R86 R87 R89 R90 R92 R96 R101-R106 R110 R111 R120 R123 = R_0603_1/10W_1%_1: Thick film; Power: 1/10W
R4 R32 R33 R37 R43 R45-R47 R83 = R_1206_1/4W_1%_1: Thick film
R5 R7 R11 R12 R25-R27 R39-R42 R60 R63 R64 R66 R76-R78 R82 R84 R85 R88 R91 R93-R95 R97-R100 R107 R108 R122 = R_0603_1/10W_1%_1: Thick film
R51-R53 R55 = R_2512_1: Thick film
R59 R67 = R_0402_1/16W_1%_1: Thick film; Power: 1/16W
R109 = R_NTC_5R_2A_P5mm: 10kΩ 电阻精度:±0.5% 3380K  NTCG163JX103DT1S
SW1 = SW_TH_4P_L6.0W6.0_P3.9_LS6.5: TH 3.9*6.5; BOM_Manufacturer: Yuandi(台湾元迪); Contributor: LCSC
TP40 = TEST-SMD: 测试点/测试环,5017
U1 = U_SPD1179: 32-bit ARM CM4 automotives MCU with HV power management, LIN and PDRV; Manufacture: Spintrol
U2 = U_LDO_EQ5430
U3 = U_TJA1044GT/3: CAN transceiver CAN FD
U4 U5 = U_LM2904DT: Manufacturer: ST(意法半导体); Add into BOM: yes; Amplifier Type: General Purpose; Number of Circuits: 2; Gain Bandwidth Product（GBP）: 1.1MHz; Slew Rate（SR）: 0.6 V/us; Supply Voltage（Single）: 3V ~ 32V, ±1.5V ~ 16V; Iq per channel (Typ): 700μA
Y1 = Z_32MHz_SMD: Part_number: AD-CJ13-320001010D05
